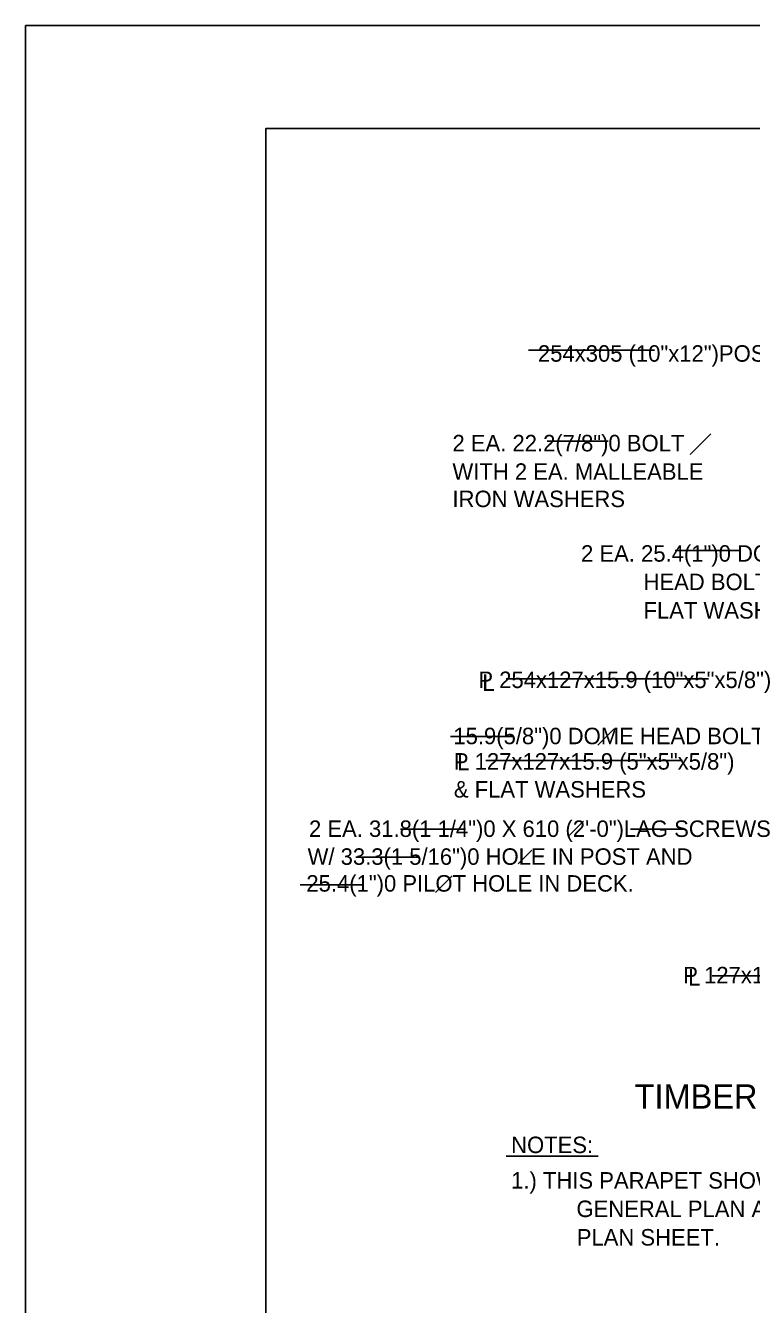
# Model space of a CAD drawing. Extents: x 179 to 454, y -271 to 54.
# Drawn here: x 360.76 to 366.05, y -9.31 to 0 of the extents above; entities that cross this region are included whole.
import ezdxf

# ---------------------------------------------------------------- set-up
doc = ezdxf.new("R2010")
doc.units = 0
for name, color, linetype in [('Level 1', 7, 'Continuous'), ('Level 2', 7, 'Continuous'), ('Level 3', 7, 'Continuous'), ('Level 41', 7, 'Continuous'), ('Level 62', 7, 'Continuous'), ('Level 63', 7, 'Continuous')]:
    doc.layers.add(name, color=color, linetype=linetype)

msp = doc.modelspace()

# ---------------------------------------------------------------- linework, layer by layer
at = {"layer": 'Level 1'}
msp.add_lwpolyline([(362.5132, -21.25), (394.0132, -21.25), (394.0132, -0.75), (362.5132, -0.75)], close=True, dxfattribs=at)
at = {"layer": 'Level 3'}
for p, q in [((365.6055, -3.1232), (365.7555, -2.9732)), ((364.9319, -5.241), (365.0511, -5.1218)), ((364.7233, -5.8968), (364.8278, -5.7923)), ((364.3514, -6.1048), (364.4514, -6.0048)), ((363.7494, -6.3123), (363.8707, -6.191)), ((364.265, -8.2322), (364.9342, -8.2322))]:
    msp.add_line(p, q, dxfattribs=at)
at = {"layer": 'Level 41'}
for p, q in [((364.4264, -2.3628), (365.3455, -2.3628)), ((364.5616, -3.0255), (365.0076, -3.0255)), ((365.4942, -3.8235), (365.9673, -3.8235)), ((364.2642, -4.7568), (365.7375, -4.7568)), ((363.8587, -5.1761), (364.3183, -5.1761)), ((364.1155, -5.3519), (365.5482, -5.3519)), ((363.4938, -5.8524), (363.9668, -5.8524)), ((365.1698, -5.8524), (365.5618, -5.8524)), ((363.1694, -6.0553), (363.6289, -6.0553)), ((362.7639, -6.2582), (363.2234, -6.2582)), ((365.7645, -6.9209), (367.2243, -6.9209))]:
    msp.add_line(p, q, dxfattribs=at)
at = {"layer": 'Level 62'}
msp.add_line((360.7633, 0), (360.7633, 0), dxfattribs=at)
at = {"layer": 'Level 63'}
msp.add_lwpolyline([(360.7633, -22), (394.7633, -22), (394.7633, 0), (360.7633, 0)], close=True, dxfattribs=at)

# ---------------------------------------------------------------- texts
at = {"layer": 'Level 2'}
msp.add_text('TIMBER POST, BRIDGE RAIL AND CURB DETAIL', height=0.177167, dxfattribs=at).set_placement((365.1997, -7.8868))
at = {"layer": 'Level 3'}
for s, p in [('254x305 (10"x12")POST', (364.4956, -2.4477)), ('2 EA. 22.2(7/8")0 BOLT', (363.8729, -3.1005)), ('WITH 2 EA. MALLEABLE', (363.8729, -3.3077)), ('IRON WASHERS', (363.8729, -3.5067)), ('2 EA. 25.4(1")0 DOME', (364.8096, -3.9038)), ('HEAD BOLTS WITH', (365.2646, -4.111)), ('FLAT WASHERS', (365.2646, -4.3182)), ('P 254x127x15.9 (10"x5"x5/8")', (364.0616, -4.8241)), ('L', (364.0906, -4.8447)), ('15.9(5/8")0 DOME HEAD BOLT WITH', (363.8794, -5.2331)), ('P 127x127x15.9 (5"x5"x5/8")', (363.883, -5.4182)), ('L', (363.9062, -5.4225)), ('& FLAT WASHERS', (363.883, -5.6215)), ('2 EA. 31.8(1 1/4")0 X 610 (2\'-0")LAG SCREWS', (362.8279, -5.9084)), ('W/ 33.3(1 5/16")0 HOLE IN POST AND', (362.8178, -6.1113)), ('25.4(1")0 PILOT HOLE IN DECK.', (362.8087, -6.3066)), ('P 127x127x15.9 (5"x5"x5/8")', (365.554, -6.9744)), ('L', (365.5888, -6.9904)), ('NOTES:', (364.3003, -8.2106)), ('1.) THIS PARAPET SHOWN ON THE', (364.3003, -8.4693)), ('GENERAL PLAN AND FRAMING', (364.7761, -8.6765)), ('PLAN SHEET.', (364.7782, -8.8837))]:
    msp.add_text(s, height=0.12, dxfattribs=at).set_placement(p)

doc.saveas('drawing.dxf')
